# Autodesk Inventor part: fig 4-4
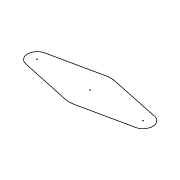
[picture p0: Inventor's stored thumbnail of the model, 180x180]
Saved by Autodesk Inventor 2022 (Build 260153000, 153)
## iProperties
Created: 2005-02
Part Number: fig 4-4
Document SubType Name: Modeling
Designer: CADCIM
Manufacturer: Standard
Standards Organization: Custom
Density: 1 g/cm^3
Material: Generic
Appearance: Default
Author: CADCIM
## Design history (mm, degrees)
sketch "Sketch1"
  geometry: L1 (-33.874, 5.844)-(-2.722, 12.469); L2 (2.595, 12.472)-(33.871, 5.852); L3 (-33.884, -5.902)-(-2.745, -12.585); L4 (2.595, -12.592)-(33.871, -5.972); A1 r 6.006 centre (-32.624, -0.03) between (-33.874, 5.844) and (-33.884, -5.902); A2 r 6.043 centre (32.619, -0.06) between (33.871, -5.972) and (33.871, 5.852); A3 r 12.81 centre (-0.057, -0.06) between (-2.745, -12.585) and (2.595, -12.592); A4 r 12.81 centre (-0.057, -0.06) between (2.595, 12.472) and (-2.722, 12.469)
  constraints: 8 end point, 8 point on circle, 8 tangent, 4 centre point, 1 other
